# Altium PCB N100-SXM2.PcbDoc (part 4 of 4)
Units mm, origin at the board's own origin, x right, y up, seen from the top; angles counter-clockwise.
Board outline 120 x 145 mm, 4 copper layers (Top Layer, GND, PWR, Bottom Layer), stack 0.603 mm thick; 267 components, 207 nets, 1440 pads, 915 vias.
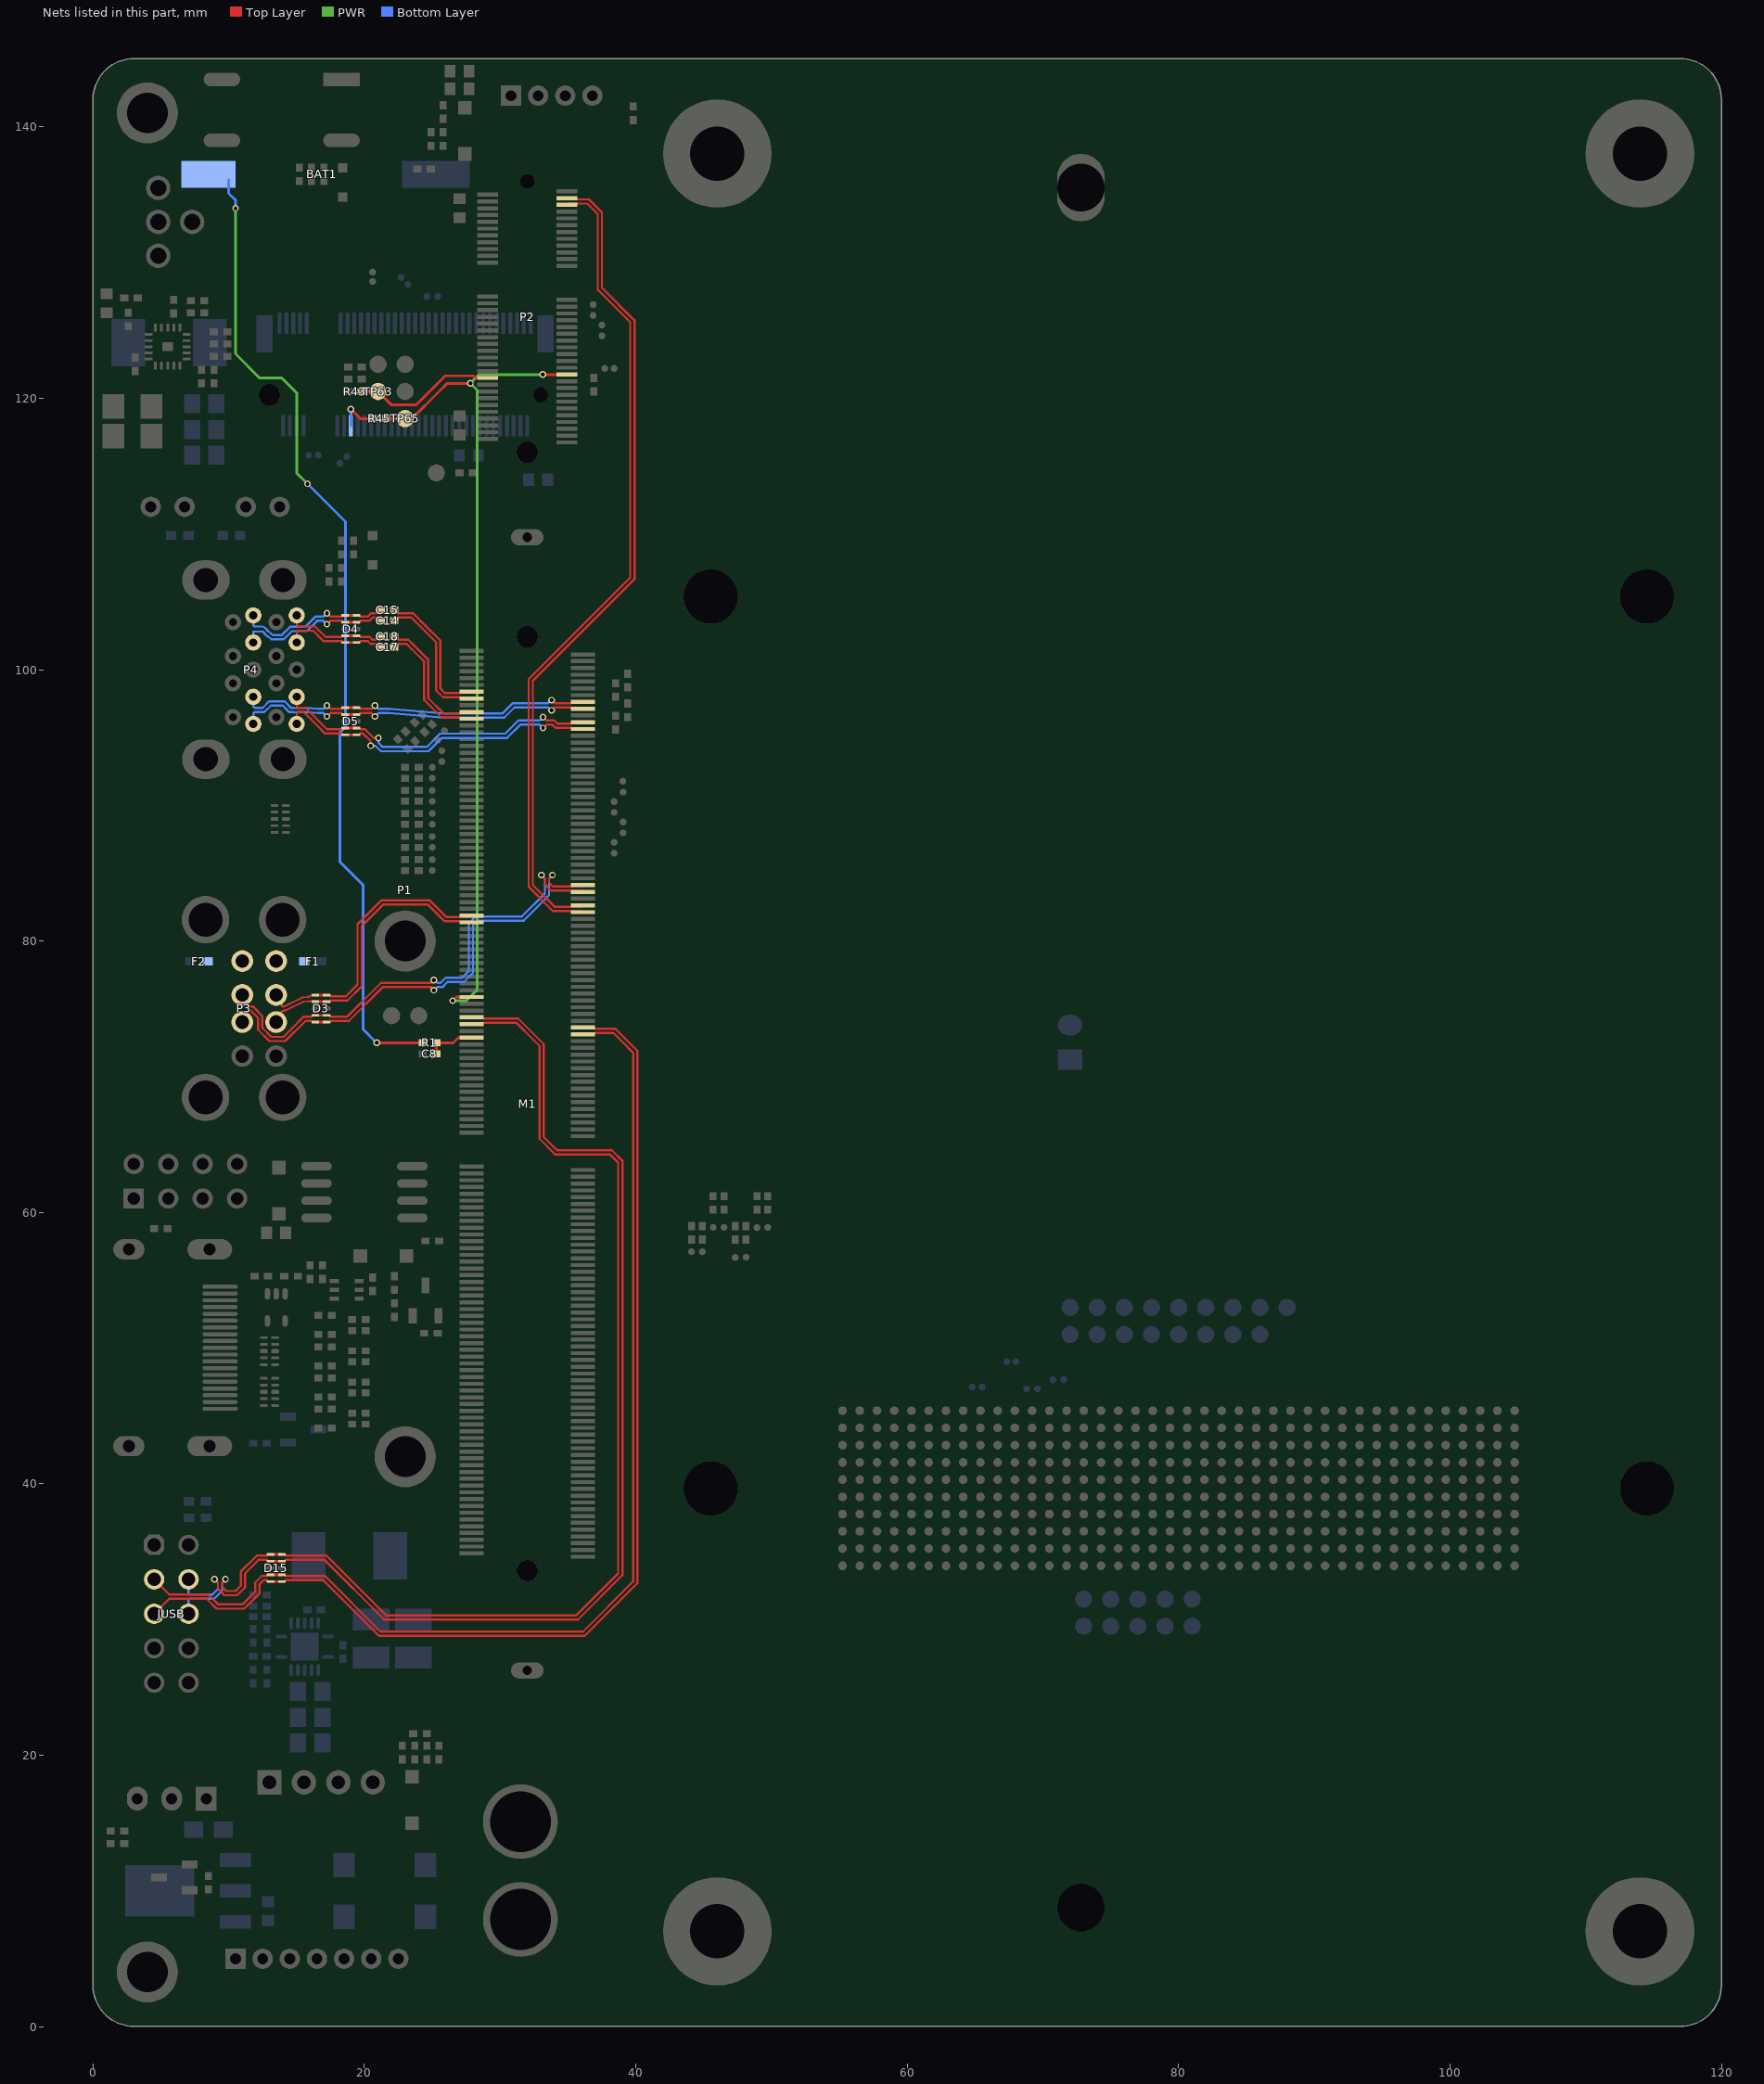
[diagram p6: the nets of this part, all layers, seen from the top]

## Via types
v1: diameter 0.5, hole 0.3, Top Layer to Bottom Layer, tented both sides, 908 vias
v2: diameter 0.6, hole 0.3, Top Layer to Bottom Layer, tented both sides, 6 vias
v3: diameter 1.5, hole 1.5, Top Layer to Bottom Layer, tented both sides, 1 vias

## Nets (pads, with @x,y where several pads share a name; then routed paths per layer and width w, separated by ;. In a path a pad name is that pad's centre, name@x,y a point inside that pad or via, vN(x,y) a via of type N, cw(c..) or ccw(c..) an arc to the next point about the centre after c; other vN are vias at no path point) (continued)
USB_3_n: D3.1 D3.10 M1.79 P3.2 | length 21.2
  Top Layer w0.161: P3.2@13.5,76.025 13.895,75.267 ccw(c14.037,75.342) 14.037,75.181 ; 14.038,75.181 ccw(c14.037,75.342) 14.1,75.193 15.353,75.806 cw(c15.491,75.528) 15.461,75.837 15.835,75.876 ; 15.836,75.876 ccw(c15.818,76.036) 15.877,75.886 16.18,76.006 D3.1@16.382,76.025 ; D3.10@17.218,76.025 17.401,76.025 17.495,75.931 18.631,75.931 19.489,76.789 19.489,81.229 21.271,83.011 24.789,83.011 25.092,82.708 25.2,82.6 26.02,81.78 27.011,81.78 27.036,81.805 27.831,81.805 M1.79@27.9,81.875
  Top Layer w0.2: D3.1@16.382,76.025 D3.10@17.218,76.025
USB_3_p: D3.2 D3.9 M1.81 P3.3 | length 21.2
  Top Layer w0.161: P3.3@13.5,74.025 13.895,74.783 ; 13.895,74.783 cw(c14.037,74.709) 14.037,74.87 ccw(c14.037,75.342) 14.221,74.907 ccw(c14.1,75.193) 14.237,74.914 15.491,75.528 15.867,75.566 cw(c15.883,75.406) 15.89,75.567 16.382,75.545 D3.2@16.382,75.525 ; D3.9@17.218,75.525 17.401,75.525 17.495,75.62 18.759,75.62 19.8,76.66 19.8,81.1 21.4,82.7 24.66,82.7 25.891,81.469 27.011,81.469 27.036,81.444 27.831,81.444 M1.81@27.9,81.375
  Top Layer w0.2: D3.2@16.382,75.525 D3.9@17.218,75.525
USB_4_n: D3.4 D3.7 M1.72 P3.6 | length 36.3
  Top Layer w0.161: P3.6@11,76.025 11,75.676 11.495,75.181 11.757,75.181 12.47,74.468 12.47,73.598 13.132,72.936 14.036,72.936 14.7,73.6 14.7,73.598 15.532,74.431 15.729,74.431 16.105,74.431 16.2,74.525 D3.4@16.382,74.525 ; D3.7@17.218,74.525 17.401,74.525 17.495,74.431 18.731,74.431 21.211,76.911 24.9,76.911 v1(25.12,77.131) ; v1(33.05,84.864) 33.05,84.844 33.295,84.6 33.295,84.171 33.746,83.719 35.211,83.719 35.236,83.694 36.03,83.694 M1.72@36.1,83.625
  Top Layer w0.2: D3.4@16.382,74.525 D3.7@17.218,74.525
  Bottom Layer w0.161: v1(25.12,77.131) 25.164,77.131 25.383,76.911 25.611,76.911 26,77.3 27.2,77.3 27.689,77.789 27.689,81.289 28.211,81.811 31.606,81.811 33.295,83.5 33.295,84.6 33.05,84.844 v1(33.05,84.864)
USB_4_p: D3.5 D3.6 M1.70 P3.7 | length 36.3
  Top Layer w0.161: P3.7@11,74.025 11,74.375 11.495,74.87 11.628,74.87 12.159,74.339 12.159,73.469 13.003,72.625 14.167,72.625 15.661,74.12 15.858,74.12 16.105,74.12 16.2,74.025 D3.5@16.382,74.025 ; D3.6@17.218,74.025 17.401,74.025 17.495,74.12 18.859,74.12 21.34,76.6 24.9,76.6 v1(25.12,76.381) ; v1(33.85,84.864) 33.85,84.844 33.606,84.6 33.606,84.3 33.875,84.03 35.211,84.03 35.236,84.055 36.03,84.055 M1.70@36.1,84.125
  Top Layer w0.2: D3.5@16.382,74.025 D3.6@17.218,74.025
  Bottom Layer w0.161: v1(25.12,76.381) 25.164,76.381 25.383,76.6 25.74,76.6 26.129,76.989 27.329,76.989 28,77.66 28,81.16 28.34,81.5 31.734,81.5 33.606,83.371 33.606,84.6 33.85,84.844 v1(33.85,84.864)
USB_B1_VBUS: F1.2 P3.1
USB_B2_VBUS: F2.2 P3.5
USB_F1_n: D15.2 D15.9 JUSB.4 M1.109 | length 90
  Top Layer w0.161: v1(8.955,32.964) 8.955,32.945 9.2,32.7 9.2,32.271 9.682,31.789 10.629,31.789 11.2,32.36 11.2,33.4 12.194,34.395 12.805,34.395 12.899,34.3 D15.2@13.082,34.3 ; D15.9@13.918,34.3 14.101,34.3 14.195,34.395 17.066,34.395 21.46,30 35.74,30 39.011,33.271 39.011,63.804 38.24,64.575 34.2,64.575 34.1,64.675 33.211,65.564 33.211,72.404 31.334,74.28 28.789,74.28 28.764,74.305 27.97,74.305 M1.109@27.9,74.375
  Top Layer w0.2: D15.2@13.082,34.3 D15.9@13.918,34.3
  Bottom Layer w0.161: JUSB.4@7.04,32.96 7.04,31.94 7.134,31.845 8.8,31.845 9.2,32.245 9.2,32.7 8.955,32.945 v1(8.955,32.964)
USB_F1_p: D15.1 D15.10 JUSB.6 M1.111 | length 88.9
  Top Layer w0.161: v1(9.755,32.964) 9.755,32.945 9.511,32.7 9.511,32.4 9.811,32.1 10.5,32.1 10.889,32.489 10.889,33.529 12.066,34.706 12.805,34.706 12.899,34.8 D15.1@13.082,34.8 ; D15.10@13.918,34.8 14.101,34.8 14.195,34.706 17.194,34.706 21.589,30.311 35.611,30.311 38.7,33.4 38.7,63.675 38.111,64.264 34.071,64.264 33.889,64.446 32.9,65.435 32.9,72.275 32.5,72.675 31.205,73.969 28.789,73.969 28.764,73.944 27.97,73.944 M1.111@27.9,73.875
  Top Layer w0.2: D15.1@13.082,34.8 D15.10@13.918,34.8
  Bottom Layer w0.161: JUSB.6@7.04,30.42 7.04,31.44 7.134,31.534 8.929,31.534 9.511,32.117 9.511,32.7 9.755,32.945 v1(9.755,32.964)
USB_F2_n: D15.4 D15.7 JUSB.3 M1.114 | length 83.9
  Top Layer w0.161: JUSB.3@4.5,32.96 5.615,31.845 8.494,31.845 9.229,31.111 11.011,31.111 11.959,32.059 11.959,32.735 12.429,33.206 12.805,33.206 12.899,33.3 D15.4@13.082,33.3 ; D15.7@13.918,33.3 14.101,33.3 14.195,33.206 17.094,33.206 21.189,29.111 36.111,29.111 39.8,32.8 39.8,71.775 39,72.575 38.355,73.219 37.216,73.219 36.989,73.219 36.964,73.194 36.169,73.194 M1.114@36.1,73.125
  Top Layer w0.2: D15.4@13.082,33.281 D15.7@13.918,33.281
USB_F2_p: D15.5 D15.6 JUSB.5 M1.112 | length 85
  Top Layer w0.161: JUSB.5@4.5,30.42 5.614,31.534 8.366,31.534 9.1,30.8 11.14,30.8 12.27,31.93 12.27,32.607 12.558,32.895 12.805,32.895 12.899,32.8 D15.5@13.082,32.8 ; D15.6@13.918,32.8 14.101,32.8 14.195,32.895 16.966,32.895 21.06,28.8 36.24,28.8 40.111,32.671 40.111,33.446 40.111,71.904 38.484,73.53 37.345,73.53 36.989,73.53 36.964,73.555 36.169,73.555 M1.112@36.1,73.625
  Top Layer w0.2: D15.5@13.082,32.8 D15.6@13.918,32.8
USB_M2_n: M1.78 P2.5 | length 61.1
  Top Layer w0.161: P2.5@34.93,134.25 34.999,134.319 35.694,134.319 35.719,134.344 36.423,134.344 37.189,133.578 37.189,128.011 39.589,125.611 39.589,106.789 32.1,99.3 32.1,84 33.881,82.219 35.211,82.219 35.236,82.194 36.03,82.194 M1.78@36.1,82.125
USB_M2_p: M1.76 P2.3 | length 61.1
  Top Layer w0.161: P2.3@34.93,134.75 34.999,134.681 35.694,134.681 35.719,134.655 36.552,134.655 37.5,133.707 37.5,128.14 39.9,125.74 39.9,106.66 32.411,99.171 32.411,84.129 34.009,82.53 35.211,82.53 35.236,82.555 36.03,82.555 M1.76@36.1,82.625
USBSS_1_RX_n: D5.4 D5.7 M1.18 P4.5 | length 26.5
  Top Layer w0.161: v1(17.236,96.55) 17.256,96.55 17.5,96.795 18.305,96.795 18.399,96.7 D5.7@18.582,96.7 ; D5.4@19.418,96.7 19.601,96.7 19.695,96.795 20.5,96.795 20.744,96.55 v1(20.764,96.55) ; v1(33.8,97) 34.019,97.219 35.193,97.219 cw(c35.193,97.177) 35.224,97.207 ccw(c35.254,97.237) 35.254,97.194 35.932,97.194 cw(c35.932,96.957) M1.18@36.1,97.125
  Top Layer w0.2: D5.7@18.582,96.7 D5.4@19.418,96.7
  Bottom Layer w0.161: P4.5@11.81,96.025 11.81,96.775 11.904,96.87 12.627,96.87 13.113,97.356 13.98,97.356 14.333,97.002 14.471,96.864 14.752,96.864 ccw(c14.91,97.994) 14.904,96.853 ccw(c14.91,98.411) 15.015,96.856 15.062,96.86 cw(c15.072,96.699) 15.066,96.86 15.07,96.86 ccw(c15.01,98) 15.168,96.87 15.641,96.87 16.574,96.796 ccw(c16.6,97.106) 16.599,96.795 ccw(c16.6,97.106) 16.6,96.794 16.972,96.795 17.217,96.55 v1(17.236,96.55) ; v1(20.764,96.55) 20.783,96.55 21.028,96.795 21.8,96.795 25.795,96.471 ccw(c25.821,96.78) 25.821,96.469 29.93,96.469 30.309,96.469 31.059,97.219 33.536,97.219 33.756,97 v1(33.8,97)
USBSS_1_RX_p: D5.5 D5.6 M1.16 P4.6 | length 26.5
  Top Layer w0.161: v1(17.236,97.35) 17.256,97.35 17.5,97.106 18.305,97.106 18.399,97.2 D5.6@18.582,97.2 ; D5.5@19.418,97.2 19.601,97.2 19.695,97.106 20.5,97.106 20.744,97.35 v1(20.764,97.35) ; v1(33.8,97.75) 34.02,97.53 35.194,97.53 ccw(c35.194,97.573) 35.224,97.543 cw(c35.254,97.513) 35.254,97.555 35.932,97.555 ccw(c35.932,97.793) M1.16@36.1,97.625
  Top Layer w0.2: D5.6@18.582,97.2 D5.5@19.418,97.2
  Bottom Layer w0.161: P4.6@11.81,98.025 11.81,97.275 11.904,97.181 12.498,97.181 12.984,97.667 14.108,97.667 14.6,97.175 14.775,97.175 ccw(c14.91,97.994) 14.909,97.164 ccw(c14.91,98.411) 15.03,97.17 ccw(c15.01,98) 15.145,97.181 15.641,97.181 cw(c15.641,97.025) 15.642,97.181 cw(c15.641,96.87) 15.667,97.179 16.6,97.106 16.972,97.106 17.217,97.35 v1(17.236,97.35) ; v1(20.764,97.35) 20.783,97.35 21.028,97.106 21.8,97.106 cw(c21.8,96.95) 21.802,97.105 cw(c21.8,96.794) 21.826,97.104 25.821,96.78 29.93,96.78 30.18,96.78 30.93,97.53 33.536,97.53 33.756,97.75 v1(33.8,97.75)
USBSS_1_TX_n: C14.2 M1.15 | length 10.3
  Top Layer w0.161: C14.2@22.2,103.6 22.246,103.6 22.49,103.845 23.455,103.845 24.517,102.783 25.289,102.011 25.289,98.471 25.791,97.969 26.994,97.969 cw(c26.994,97.927) 27.024,97.957 ccw(c27.054,97.987) 27.054,97.944 27.732,97.944 cw(c27.732,97.707) M1.15@27.9,97.875
USBSS_1_TX_p: C15.2 M1.13 | length 10.3
  Top Layer w0.161: C15.2@22.2,104.4 22.246,104.4 22.49,104.156 23.584,104.156 24.52,103.22 25.6,102.14 25.6,98.6 25.92,98.28 26.994,98.28 ccw(c26.994,98.323) 27.024,98.293 cw(c27.054,98.263) 27.054,98.305 27.732,98.305 ccw(c27.732,98.543) M1.13@27.9,98.375
USBSS_1a_TX_n: C14.1 D4.4 D4.7 P4.8 | length 11.4
  Top Layer w0.161: v1(17.236,103.35) 17.256,103.35 17.5,103.594 18.305,103.594 18.399,103.5 D4.7@18.582,103.5 ; D4.4@19.418,103.5 19.601,103.5 19.695,103.594 20.368,103.594 20.618,103.845 20.909,103.845 21.154,103.6 C14.1@21.2,103.6
  Top Layer w0.2: D4.7@18.582,103.5 D4.4@19.418,103.5
  Bottom Layer w0.161: P4.8@11.81,102.025 11.81,102.805 12.51,102.805 12.565,102.75 ccw(c13.478,103.435) 12.697,102.602 ccw(c15.466,105.563) 12.795,102.514 12.873,102.452 ccw(c14.727,104.805) 12.934,102.405 13.151,102.243 14.053,102.243 14.649,102.839 15.754,102.839 16.509,103.594 16.972,103.594 17.217,103.35 v1(17.236,103.35)
USBSS_1a_TX_p: C15.1 D4.5 D4.6 P4.9 | length 11.5
  Top Layer w0.161: v1(17.236,104.15) 17.256,104.15 17.5,103.905 18.305,103.905 18.399,104 D4.6@18.582,104 ; D4.5@19.418,104 19.601,104 19.695,103.905 20.239,103.905 20.489,104.156 20.909,104.156 21.154,104.4 C15.1@21.2,104.4
  Top Layer w0.2: D4.6@18.582,104 D4.5@19.418,104
  Bottom Layer w0.161: P4.9@11.81,104.025 11.81,103.275 11.904,103.181 12.476,103.181 12.639,103.116 12.801,102.953 ccw(c13.478,103.435) 12.914,102.825 ccw(c14.727,104.805) 13.264,102.554 13.924,102.554 14.521,103.15 15.625,103.15 16.38,103.905 16.972,103.905 17.217,104.15 v1(17.236,104.15)
USBSS_2_RX_n: D5.1 D5.10 M1.24 P4.14 | length 24.5
  Top Layer w0.161: P4.14@15.01,96.025 15.01,96.775 15.104,96.87 15.53,96.87 16.5,95.9 17.106,95.295 18.305,95.295 18.399,95.2 D5.10@18.582,95.2 ; D5.1@19.418,95.2 19.601,95.2 19.695,95.295 19.906,95.295 20.45,94.75 20.45,94.404 v1(20.464,94.391) ; v1(33.16,95.7) 33.179,95.7 33.424,95.944 33.854,95.944 34.079,95.719 35.211,95.719 35.236,95.694 36.03,95.694 M1.24@36.1,95.625
  Top Layer w0.2: D5.10@18.582,95.2 D5.1@19.418,95.2
  Bottom Layer w0.161: v1(20.464,94.391) 20.477,94.377 20.823,94.377 21.211,93.989 24.729,93.989 25.709,94.969 29.929,94.969 30.509,94.969 31.484,95.944 32.915,95.944 v1(33.16,95.7)
USBSS_2_RX_p: D5.2 D5.9 M1.22 P4.15 | length 24.5
  Top Layer w0.161: P4.15@15.01,98.025 15.01,97.275 15.104,97.181 15.659,97.181 17.234,95.606 18.305,95.606 18.399,95.7 D5.9@18.582,95.7 ; D5.2@19.418,95.7 19.601,95.7 19.695,95.606 20.034,95.606 20.67,94.97 21.016,94.97 v1(21.029,94.956) ; v1(33.16,96.5) 33.179,96.5 33.424,96.255 33.983,96.255 34.208,96.03 35.211,96.03 35.236,96.055 36.03,96.055 M1.22@36.1,96.125
  Top Layer w0.2: D5.9@18.582,95.7 D5.2@19.418,95.7
  Bottom Layer w0.161: v1(21.029,94.956) 21.043,94.943 21.043,94.597 21.34,94.3 24.6,94.3 25.58,95.28 29.93,95.28 30.38,95.28 31.355,96.255 32.915,96.255 v1(33.16,96.5)
USBSS_2_TX_n: C17.2 M1.21 | length 9.7
  Top Layer w0.161: C17.2@22.2,101.65 22.246,101.65 22.491,101.894 23.106,101.894 23.474,101.527 24.389,100.611 24.389,97.771 25.691,96.469 26.994,96.469 cw(c26.994,96.427) 27.024,96.457 ccw(c27.054,96.487) 27.054,96.444 27.732,96.444 cw(c27.732,96.207) M1.21@27.9,96.375
USBSS_2_TX_p: C18.2 M1.19 | length 9.7
  Top Layer w0.161: C18.2@22.2,102.45 22.246,102.45 22.491,102.205 23.234,102.205 23.62,101.82 23.795,101.645 24.609,100.831 24.7,100.74 24.7,97.9 25.82,96.78 26.994,96.78 ccw(c26.994,96.823) 27.024,96.793 cw(c27.054,96.763) 27.054,96.805 27.732,96.805 ccw(c27.732,97.043) M1.19@27.9,96.875
USBSS_2a_TX_n: C17.1 D4.1 D4.10 P4.17 | length 7.6
  Top Layer w0.161: P4.17@15.01,102.025 15.01,102.775 15.104,102.87 16.23,102.87 17.006,102.094 18.305,102.094 18.399,102 D4.10@18.582,102 ; D4.1@19.418,102 19.601,102 19.695,102.094 20.264,102.094 20.464,101.894 20.91,101.894 21.154,101.65 C17.1@21.2,101.65
  Top Layer w0.2: D4.10@18.582,102 D4.1@19.418,102
USBSS_2a_TX_p: C18.1 D4.2 D4.9 P4.18 | length 7.6
  Top Layer w0.161: P4.18@15.01,104.025 15.01,103.275 15.104,103.181 16.359,103.181 17.134,102.406 18.305,102.406 18.399,102.5 D4.9@18.582,102.5 ; D4.2@19.418,102.5 19.601,102.5 19.695,102.406 20.393,102.406 20.593,102.205 20.91,102.205 21.154,102.45 C18.1@21.2,102.45
  Top Layer w0.2: D4.9@18.582,102.5 D4.2@19.418,102.5
VBAT: BAT1.1 R1.1 | length 72.8
  Top Layer w0.2: v1(20.9,72.5) R1.1@24.3,72.5
  PWR w0.2: v1(10.5,134) 10.5,123.266 12.266,121.5 13.9,121.5 15,120.4 15,114.5 v1(15.8,113.7)
  Bottom Layer w0.2: BAT1.1@10,136.1 10,135.1 10.5,134.6 v1(10.5,134) ; v1(15.8,113.7) 18.6,110.9 18.6,95.766 18.2,95.366 18.2,85.834 19.9,84.134 19.9,73.5 v1(20.9,72.5)
VBAT_IN: C8.2 M1.115 R1.2 | length 3.6
  Top Layer w0.2: C8.2@25.3,71.7 R1.2@25.3,72.5 26.525,72.5 26.9,72.875 M1.115@27.9,72.875
WAKE#: M1.103 P2.55 R45.1 TP65.1 | length 63.2
  Top Layer w0.2: R45.1@21.6,118.5 TP65.1@23,118.5 23.5,118.5 25.5,120.5 26.1,121.1 v1(27.8,121.1) ; v1(26.5,75.6) 26.775,75.875 M1.103@27.9,75.875 ; v1(33.15,121.75) P2.55@34.93,121.75
  PWR w0.2: v1(26.5,75.6) 27.5,75.6 28.3,76.4 28.3,120.6 v1(27.8,121.1) 28.45,121.75 v1(33.15,121.75)
WAKE_M: P1.54 R45.2 | length 3.1
  Top Layer w0.2: v1(19,119.2) 19.7,118.5 R45.2@20.6,118.5
  Bottom Layer w0.2: P1.54@19,117.975 v1(19,119.2)
WLAN_OFF: P2.56 R43.2 TP63.1 | length 10.6
  Top Layer w0.2: R43.2@19.8,120.5 TP63.1@21,120.5 22,119.5 23.8,119.5 25.95,121.65 28.028,121.65 28.128,121.55 29.02,121.55 P2.56@29.07,121.5
pads on no net: D11.1 J2.1 J2.2 J2.3 J2.6 JUSB.9 JUSB.10 K1.2 K1.3 M1.7 M1.10 M1.12 M1.82 M1.84 M1.88 M1.90 M1.94 M1.96 M1.104 M1.117 M1.118 M1.119 M1.120 M1.121 M1.122 M1.123 M1.124 M1.125 M1.126 M1.127 M1.128 M1.129 M1.130 M1.132 M1.134 M1.137 M1.138 M1.139 M1.140 M1.141 M1.142 M1.143 M1.144 M1.145 M1.146 M1.147 M1.148 M1.149 M1.150 M1.152 M1.154 M1.156 M1.157 M1.160 M1.162 M1.164 M1.166 M1.168 M1.172 M1.173 M1.174 M1.175 M1.176 M1.177 M1.178 M1.179 M1.180 M1.184 M1.185 M1.186 M1.187 M1.190 M1.191 M1.192 M1.193 M1.196 M1.198 M1.202 M1.204 M1.208 M1.210 M1.214 M1.216 M1.220 M1.221 M1.222 M1.223 M1.226 M1.227 M1.228 M1.229 M1.232 M1.233 M1.234 M1.235 M1.238 M1.239 M1.240 M1.241 M1.244 M1.245 M1.246 M1.247 M1.261 P1.0 P1.5 P1.6 P1.7 P1.8 P1.11 P1.13 P1.17 P1.19 P1.20 P1.22 P1.23 P1.24 P1.25 P1.26 P1.28 P1.30 P1.32 P1.34 P1.36 P1.38 P1.40 P1.42 P1.44 P1.46 P1.48 P1.56 P1.58 P1.67 P1.68 P1.69 P2.0 P2.6 P2.8 P2.9 P2.10 P2.11 P2.12 P2.14 P2.15 P2.16 P2.17 P2.20 P2.21 P2.22 P2.23 P2.32 P2.34 P2.36 P2.38 P2.40 P2.42 P2.44 P2.46 P2.48 P2.58 P2.59 P2.60 P2.61 P2.62 P2.64 P2.65 P2.66 P2.67 P2.68 P2.70 P2.71 P2.73 P5.13 P5.14 P6.@45.5,39.675 P6.@45.5,105.375 P6.@46,7.025 P6.@46,138.025 P6.@72.8,8.775 P6.@72.8,135.525 P6.@114,138.025 P6.@114.5,39.675 P6.@114.5,105.375 P6.A2 P6.A3 P6.A5 P6.A6 P6.A8 P6.A9 P6.B1 P6.B2 P6.B4 P6.B5 P6.B9 P6.B10 P6.C2 P6.C3 P6.C5 P6.C6 P6.C8 P6.C9 P6.C15 P6.D1 P6.D2 P6.D4 P6.D5 P6.D9 P6.D10 P6.G1 P6.G2 P6.G4 P6.G5 P6.G9 P6.G10 P6.H2 P6.H3 P6.H5 P6.H6 P6.H8 P6.H9 P6.J1 P6.J2 P6.J4 P6.J5 P6.J7 P6.J9 P6.J10 P6.K2 P6.K3 P6.K5 P6.K6 P6.K8 P6.K9 P6.K39 U2.9 U2.11 U4.14
copper on no net:
  other v3: 1.7,133

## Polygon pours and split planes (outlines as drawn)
+3V3 on Top Layer "+3V3_L01_P159" (solid, pour order 159): 28.1,136.3 22,136.3 15.3,129.6 15.3,120 14.3,119 10.5,119 10.5,114.7 11.2,114 14.9,114 17.9,111 19.5,111 19.9,110.6 33.3,110.6 33.5,110.8 33.5,113.1 33.1,113.5 30.6,113.5 30,114.1 24.8,114.1 24.5,114.4 24.5,114.7 25.2,115.4 27.1,115.4 28.1,116.4 28.1,118 19.4,118 18.2,119.2 18.2,123.096 18.196,123.1 17.5,123.1 17.5,127.6 24,134.1 28.1,134.1
5V_HDMI on Top Layer "5V_HDMI_L01_P067" (solid, remove dead copper, pour order 67): 20.3,57.4 18.9,57.4 18,56.5 10.9,56.5 10.6,56.2 7,56.2 6.3,56.9 6.3,59 6.1,59.2 5.1,59.2 5.1,54.9 6.2,53.8 7.8,53.8 7.8,54.7 8,54.9 10.5,54.9 11.4,55.8 20.3,55.8
USB_1_VBUS on Top Layer "USB_1_VBUS_L01_P154" (solid, pour order 154): 7.7,113 5.2,113 5.2,111.6 4.7,111.1 4.7,103.5 5.7,102.5 10.7,102.5 11.1,102.9 11.1,103.8 10.2,104.7 7.3,104.7 6.3,105.7 6.3,111.1 6.4,111.2 7.7,111.2
USB_2_VBUS on Top Layer "USB_2_VBUS_L01_P153" (solid, pour order 153): 10.5,113 12.4,113 12.4,105.9 13.4,104.9 14.2,104.9 14.2,102.829 14.065,102.695 13.166,102.695 11.8,104.061 11.8,104.8 10.9,104.8 10.3,105.4 10.3,112.8
GND on Top Layer "GND_L01_P151" (solid, pour order 151): 0,129.1 9.5,129.1 10.3,128.3 15.1,128.3 15.1,129.7 21.9,136.5 24.3,136.5 24.3,145 0,145
GND on Top Layer "GND_L01_P145" (solid, pour order 145): 28.1,118.2 28.1,120.3 25.8,120.3 24.2,118.7 24.2,118.2 27.6,118.2
GND on Top Layer "GND_L01_P143" (solid, pour order 143): 19.7,123.3 20.3,123.9 28,123.9 28,128.2 21.2,128.2 20.1,127.1 17.6,127.1 17.7,127 17.7,123.3
GND on Top Layer "GND_L01_P142" (solid, pour order 142): 28,133.9 24.1,133.9 20.5,130.3 20.5,130 28,130
GND on Top Layer "GND_L01_P135" (solid, pour order 135): 0,0 0,29 10.7,29 13.2,31.5 17.3,31.5 20.7,28.1 39.9,28.1 42,30.2 42,44.2 42.6,44.8 45.3,44.8 48.5,41.6 48.5,31.7 51.7,28.5 67,28.5 69.8,31.3 69.8,35.1 81.2,35.1 81.2,31.6 69.3,19.7 41.2,19.7 33,11.5 26.4,11.5 25.3,10.4 25.3,0
GND on Top Layer "GND_L01_P127" (solid, remove dead copper, pour order 127): 3.2,125.7 7.5,125.7 7.5,115.2 3,115.2 3,121.4 2.8,121.6 2.8,123.7 3.2,124.1
3V3_SW on Top Layer "3V3_SW_L01_P126" (solid, remove dead copper, pour order 126): 3.7,126.3 5.2,126.3 5.2,123 4.9,122.7 4.9,121.3 4.4,121.3 3.7,122
+12V_IN on Top Layer "+12V_IN_L01_P125" (solid, remove dead copper, pour order 125): 4.4,124.4 3.1,124.4 2.7,124.8 0.5,124.8 0.5,108.6 2.8,108.6 2.8,121.3 2.6,121.5 2.6,122.4 2.8,122.6 3.6,122.6 3.8,122.8 4.4,122.8
+12V_IN on Top Layer "+12V_IN_L01_P117" (solid, remove dead copper, pour order 117): 5.5,65.5 5.5,85.9 4.5,86.9 4.5,108.2 1.7,111 0.5,111 0.5,65.5
GND on Top Layer "GND_L01_P115" (solid, remove dead copper, pour order 115): 1.2,59.2 11.5,59.2 11.5,41.5 1.2,41.5
GND on Top Layer "GND_L01_P095" (solid, remove dead copper, pour order 95): 54,51.5 81.2,51.5 81.2,32.8 54,32.8
+12V_IN on Top Layer "+12V_IN_L01_P059" (solid, remove dead copper, pour order 59): 25.5,0 25.5,10.3 26.5,11.3 33.1,11.3 41.3,19.5 69.375,19.5 81.4,31.525 81.4,51 119.5,51 119.5,12 111.9,12 109,9.1 109,0
+12V_CPU on Top Layer "NONET_L-01_P-001" (solid, remove dead copper, pour order 58): 36.975,34.475 27.025,34.475 27.025,37.025 32.025,37.025 32.275,37.275 36.975,37.275
GND on Bottom Layer "GND_L04_P158" (solid, pour order 158): 0,114.8 15.3,114.8 15.3,113.8 18.3,110.8 18.3,105.2 11,105.2 11,95 17.9,95 17.9,83 0,83
GND on Bottom Layer "GND_L04_P156" (solid, pour order 156): 0,125.8 17.8,125.8 17.8,127.5 18.3,128 20.8,128 23.5,130.7 38,130.7 38,145 0,145
USB_1_VBUS on Bottom Layer "USB_1_VBUS_L04_P155" (solid, pour order 155): 7.7,113 5.2,113 5.2,111.6 4.7,111.1 4.7,103.5 5.7,102.5 10.7,102.5 11.1,102.9 11.1,103.8 10.2,104.7 7.3,104.7 6.3,105.7 6.3,111.1 6.4,111.2 7.7,111.2
+3V3 on Bottom Layer "+3V3_L04_P149" (solid, pour order 149): 7.3,126 10.8,126 10.8,123 11,122.8 13.1,122.8 15.2,120.7 15.2,117.1 15.2,114.4 14.8,114 8.9,114 8.3,114.6 8.3,121 7.3,122 7.3,122.7
USB_2_VBUS on Bottom Layer "USB_2_VBUS_L04_P148" (solid, pour order 148): 10.5,113 12.4,113 12.4,105.9 13.4,104.9 14.2,104.9 14.2,102.829 14.065,102.695 13.166,102.695 11.8,104.061 11.8,104.8 10.9,104.8 10.3,105.4 10.3,112.8
GND on Bottom Layer "GND_L04_P147" (solid, pour order 147): 72.6,48.6 72.6,49.4 71,51 71,62 106.3,62 106.3,48.6
GND on Bottom Layer "GND_L04_P139" (solid, pour order 139): 27.6,116.9 19.3,116.9 19.3,115.9 23.9,111.3 23.9,102.2 27.2,102.2 30,105 30,110 27.6,112.4 27.6,114.6
+3V3 on Bottom Layer "+3V3_L04_P138" (solid, pour order 138): 27.8,118.9 34,118.9 34.3,118.6 34.3,111.5 33.5,110.7 29.6,110.7 27.8,112.5
GND on Bottom Layer "GND_L04_P137" (solid, pour order 137): 29.5,116 31.4,116 32.7,114.7 32.7,113.5 32.6,113.4 30.9,113.4 29.3,115 29.3,115.8
GND on Bottom Layer "NONET_L-01_P-001" (solid, remove dead copper, pour order 121): 11,123 34.3,123 34.3,127 11,127
GND on Bottom Layer "GND_L04_P134" (solid, remove dead copper, pour order 134): 0,0 0,83.5 29.9,83.5 29.9,78.5 30.7,77.7 45.6,77.7 62.7,60.6 62.7,49.2 64,47.9 64,46.7 64.2,46.5 72,46.5 72.6,47.1 72.6,49.2 120,49.2 120,0
+12V_IN on Bottom Layer "+12V_IN_L04_P132" (solid, remove dead copper, pour order 132): 27.2,10.7 17.7,10.7 17.4,11 17.4,16.9 16.9,17.4 16.9,19.2 16,20.1 16,25.6 15.8,25.8 15.8,26.7 14.4,26.7 14,26.3 14,24.9 13.1,24 13.1,19.4 13.3,19.2 14.1,19.2 14.2,19.1 14.2,10.4 15.4,9.2 19.4,9.2 19.6,9 19.6,6.3 27.2,6.3
+12V_CPU on Bottom Layer "+12V_CPU_L04_P131" (solid, remove dead copper, pour order 131): 26.8,10.9 26.8,21.3 30.5,25 30.5,27 30.9,27.4 30.9,34 31.9,35 31.9,36.8 31.6,37.1 28.1,37.1 26.9,35.9 26.9,29.5 25.8,28.4 25.8,25.9 22.3,22.4 22.3,16.3 20.5,14.5 17.6,14.5 17.6,10.9
+5V on Bottom Layer "+5V_L04_P130" (solid, remove dead copper, pour order 130): 7.8,39.3 9,40.5 20.1,40.5 23.8,36.8 25.1,36.8 26.7,35.2 26.7,29.6 25.8,28.7 18.6,28.7 18.6,36.7 18.1,37.2 12.7,37.2 12.2,36.7 8.1,36.7 7.8,37
GND on Bottom Layer "GND_L04_P128" (solid, remove dead copper, pour order 128): 8.1,114.8 8.1,120.9 7.1,121.9 7.1,127.6 0,127.6 0,114.8
3V3_SW on Bottom Layer "3V3_SW_L04_P124" (solid, remove dead copper, pour order 124): 5.1,126.3 5.3,126.1 5.3,125 5.1,124.8 5.1,122.1 4.9,121.9 4.9,121.5 4.7,121.3 2.2,121.3 1.2,122.3 1.2,126.1 1.4,126.3
5V_SW on Bottom Layer "5V_SW_L04_P122" (solid, remove dead copper, pour order 122): 16.3,29.3 16.3,31 16.5,31.2 17.7,31.2 17.7,36.8 13.9,36.8 13.9,31.5 14.5,30.9 14.9,30.9 15.4,30.4 15.4,29.3
FUSB_VBUS2 on Bottom Layer "FUSB_VBUS2_L04_P113" (solid, remove dead copper, pour order 113): 5.6,34.7 5.6,37.7 6.1,38.2 7.6,38.2 7.6,39.3 5.5,39.3 3.5,37.3 3.5,34.7 3.9,34.3 5.2,34.3
FUSB_VBUS1 on Bottom Layer "FUSB_VBUS1_L04_P112" (solid, remove dead copper, pour order 112): 7.7,34.3 8.2,34.8 8.2,36.1 7.6,36.7 7.6,38 6.3,38 6,37.7 6,34.7 6.4,34.3
USB_B1_VBUS on Bottom Layer "USB_B1_VBUS_L04_P107" (solid, remove dead copper, pour order 107): 12.5,79.5 12.5,77.5 16.1,77.5 16.1,79.5
USB_B2_VBUS on Bottom Layer "USB_B2_VBUS_L04_P106" (solid, remove dead copper, pour order 106): 12,77.5 12,79.5 8,79.5 8,77.5
+3V3_SB on Bottom Layer "+3V3_SB_L04_P104" (solid, remove dead copper, pour order 104): 9,7 9,8.4 9.3,8.7 12,8.7 12,11.3 9.2,11.3 8.4,12.1 8.4,15.3 1.5,15.3 1.5,7.4 1.9,7
+12V_IN on Bottom Layer "+12V_IN_L04_P061" (solid, remove dead copper, pour order 61): 27,11.3 36,11.3 37.1,12.4 44.2,19.5 74.4,19.5 81.4,26.5 81.4,42 119.5,42 119.5,12 111.9,12 109,9.1 109,0.3 27,0.3
no net on Bottom Layer "NONET_L-01_P-001" (solid, remove dead copper, pour order 16): 112.9,12.725 112.9,13.525 cw(c113.3,13.525) 113.3,13.925 114.1,13.925 cw(c114.1,13.525) 114.5,13.525 114.5,12.725 cw(c114.1,12.725) 114.1,12.325 113.3,12.325 cw(c113.3,12.725)
GND on PWR "NONET_L-01_P-001" (solid, remove dead copper, pour order 157): 0,0 120,0 120,145 0,145
+5V on PWR "+5V_L03_P152" (solid, pour order 152): 14.5,77 0,77 0,111 10.5,111 10.5,105.5 9.2,104.2 9.2,97.8 11.8,95.2 11.8,92.3 14.5,89.6 14.5,86.8
+5V on PWR "+5V_L03_P118" (solid, remove dead copper, pour order 118): 5.5,77 5.5,91.5 15.8,91.5 28,91.5 28,35.1 30.7,32.4 58.3,32.4 60.2,30.5 72.3,30.5 73.3,29.5 78.5,29.5 79,30 79,38.4 78.3,39.1 78.3,39.9 78.6,40.2 82.1,40.2 82.7,39.6 82.7,33.3 84.2,31.8 84.2,27.2 79.9,22.9 27.4,22.9 18.5,31.8 18.5,48.1 18.5,73 14.5,77
+12V_IN on PWR "+12V_IN_L03_P119" (solid, remove dead copper, pour order 119): 0,68.5 4.9,68.5 7,66.4 18.3,66.4 18.3,28.4 24,22.7 24,14.9 27.9,11 33.8,11 35,9.8 35,4.1 34.3,3.4 26.3,3.4 23.4,6.3 7.7,6.3 6.2,7.8 0,7.8
GND on GND "NONET_L-01_P-001" (solid, remove dead copper, pour order 60): 0,0 120,0 120,145 0,145

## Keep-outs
Keep-Out Layer:
  circle w0.1: c45.5,39.675 r2.5
  circle w0.1: c114.5,39.675 r2.5
  lines w0.1: 0,3.025 ccw(c3,3.025) 3,0.025 117,0.025 ccw(c117,3.025) 120,3.025 120,142.025 ccw(c117,142.025) 117,145.025 3,145.025 ccw(c3,142.025) 0,142.025 0,3.025

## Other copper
Top Layer:
  drawing of 2289 lines, arcs and shapes, not listed
GND:
  region net +5V: 10.1,111 6.5,111 6.5,108.8 10.1,108.8
  rectangle net +3V3: 30.2,111 33.2,113.2
  rectangle net +12V_IN: 0.7,65.7 3.4,67.7
  rectangle net +3V3: 11.3,115.4 13.3,118.1
  rectangle net +5V: 17,77.5 18.4,79.5
  rectangle net +5V: 6.1,77.5 7.5,79.5
  rectangle net +12V_IN: 21.2,7.3 23.4,10.3
  rectangle net +12V_CPU: 29.7,34.8 31.7,36.8
  rectangle net +5V: 23.4,31.2 26.4,34.2
  region net 3V3_SW: 4.4,126.3 5,126.3 cw(c5,126) 5.3,126 5.3,125.4 5.1,125.2 5.1,122.6 4.9,122.4 4.9,121.6 cw(c4.6,121.6) 4.6,121.3 cw(c4.6,121.541) 4.429,121.371 4.012,121.788 cw(c4.524,122.3) 3.8,122.3 3.8,125.517 cw(c4.483,125.517) 4,126 4.229,126.229 cw(c4.4,126.059)
  pour cut-out: 48.675,59.9 48.675,61.5 49.175,61.5 49.175,59.9
  pour cut-out: 49.475,59.9 49.475,61.5 49.975,61.5 49.975,59.9
  pour cut-out: 47.075,57.7 47.075,59.3 47.575,59.3 47.575,57.7
  pour cut-out: 47.875,57.7 47.875,59.3 48.375,59.3 48.375,57.7
  pour cut-out: 45.45,59.9 45.45,61.5 45.95,61.5 45.95,59.9
  pour cut-out: 46.25,59.9 46.25,61.5 46.75,61.5 46.75,59.9
  pour cut-out: 25.026,95.577 23.895,96.708 24.248,97.062 25.38,95.93
  pour cut-out: 24.46,95.011 23.329,96.142 23.683,96.496 24.814,95.365
  pour cut-out: 23.206,93.775 22.075,94.906 22.428,95.26 23.56,94.128
  pour cut-out: 23.772,94.34 22.64,95.472 22.994,95.825 24.125,94.694
  pour cut-out: 22.7,86.25 24.3,86.25 24.3,85.75 22.7,85.75
  pour cut-out: 22.7,85.45 24.3,85.45 24.3,84.95 22.7,84.95
  pour cut-out: 22.7,87.95 24.3,87.95 24.3,87.45 22.7,87.45
  pour cut-out: 22.7,87.15 24.3,87.15 24.3,86.65 22.7,86.65
  pour cut-out: 22.7,92.275 24.3,92.275 24.3,91.775 22.7,91.775
  pour cut-out: 22.7,93.075 24.3,93.075 24.3,92.575 22.7,92.575
  pour cut-out: 22.7,90.575 24.3,90.575 24.3,90.075 22.7,90.075
  pour cut-out: 22.7,91.375 24.3,91.375 24.3,90.875 22.7,90.875
  pour cut-out: 22.7,88.85 24.3,88.85 24.3,88.35 22.7,88.35
  pour cut-out: 22.7,89.65 24.3,89.65 24.3,89.15 22.7,89.15
  region net +12V_IN: 83.429,41.072 83.429,38.278 82.667,37.516 82.413,37.516 81.651,38.278 81.651,41.072 82.413,41.834 82.667,41.834
  region net +12V_IN: 87.239,41.072 87.239,38.278 86.477,37.516 86.223,37.516 85.461,38.278 85.461,41.072 86.223,41.834 86.477,41.834
  region net +12V_IN: 91.049,41.072 91.049,38.278 90.287,37.516 90.033,37.516 89.271,38.278 89.271,41.072 90.033,41.834 90.287,41.834
  region net +12V_IN: 94.859,41.072 94.859,38.278 94.097,37.516 93.843,37.516 93.081,38.278 93.081,41.072 93.843,41.834 94.097,41.834
  region net +12V_IN: 98.669,41.072 98.669,38.278 97.907,37.516 97.653,37.516 96.891,38.278 96.891,41.072 97.653,41.834 97.907,41.834
  region net +12V_IN: 102.479,41.072 102.479,38.278 101.717,37.516 101.463,37.516 100.701,38.278 100.701,41.072 101.463,41.834 101.717,41.834
  pour cut-out: 44.65,57.7 44.65,59.3 45.15,59.3 45.15,57.7
  pour cut-out: 43.85,57.7 43.85,59.3 44.35,59.3 44.35,57.7
PWR:
  rectangle net +3V3: 30.2,111 33.2,113.2
  rectangle net +3V3: 11.3,115.4 13.3,118.1
  rectangle net +12V_CPU: 29.7,34.8 31.7,36.8
  region net 3V3_SW: 4.4,126.3 5,126.3 cw(c5,126) 5.3,126 5.3,125.4 5.1,125.2 5.1,122.6 4.9,122.4 4.9,121.6 cw(c4.6,121.6) 4.6,121.3 cw(c4.6,121.541) 4.429,121.371 4.012,121.788 cw(c4.524,122.3) 3.8,122.3 3.8,125.517 cw(c4.483,125.517) 4,126 4.229,126.229 cw(c4.4,126.059)
  region net GND: 17.9,26.6 18.5,26 24,26 24.2,25.8 24.2,24.9 24,24.7 18.8,24.7 18.4,24.3 18.4,23.4 18.2,23.2 18,23.2 17.8,23.4 17.8,25.1 17.5,25.4 17,25.4 16.8,25.6 16.8,26.4 17,26.6
  region net GND: 15.7,29 16.6,28.1 16.6,27.9 15.7,27 15.5,27 14.6,27.9 14.6,28.1 15.5,29
  region net +12V_IN: 102.479,41.072 102.479,38.278 101.717,37.516 101.463,37.516 100.701,38.278 100.701,41.072 101.463,41.834 101.717,41.834
  region net +12V_IN: 98.669,41.072 98.669,38.278 97.907,37.516 97.653,37.516 96.891,38.278 96.891,41.072 97.653,41.834 97.907,41.834
  region net +12V_IN: 94.859,41.072 94.859,38.278 94.097,37.516 93.843,37.516 93.081,38.278 93.081,41.072 93.843,41.834 94.097,41.834
  region net +12V_IN: 91.049,41.072 91.049,38.278 90.287,37.516 90.033,37.516 89.271,38.278 89.271,41.072 90.033,41.834 90.287,41.834
  region net +12V_IN: 87.239,41.072 87.239,38.278 86.477,37.516 86.223,37.516 85.461,38.278 85.461,41.072 86.223,41.834 86.477,41.834
  region net +12V_IN: 83.429,41.072 83.429,38.278 82.667,37.516 82.413,37.516 81.651,38.278 81.651,41.072 82.413,41.834 82.667,41.834
Bottom Layer:
  drawing of 1590 lines, arcs and shapes, not listed
  text "20250211-REV.A2" at 118.525,70.748 h5 r90

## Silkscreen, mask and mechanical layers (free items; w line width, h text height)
Top Overlay:
  drawing of 81 lines, arcs and shapes, not listed
  text "RESET" at 20.127,144.513 h2.5 r270
  text "PWR SW" at 10.027,137.416 h2.5 r270
  text "CPU_FAN" at 28.634,137.244 h2.5
  text "M.2 E-KEY" at 25.2,131.432 h2.5 r270
  text "M.2_SSD ACT" at 3.9,126.9 h1.52
  text "PERST#" at 15.5,124.5 h1.5
  text "CLKREQ" at 22.6,112.5 h1.52
  text "DATA" at 19.1,75.5 h1.52
  text "CLK" at 23,75.5 h1.52
  text "SMBus" at 18.7,72.7 h1.52
  text "JBIOS" at 11.795,29.127 h2.5
  text "1-2 INT ROM" at 11.8,26.827 h2.5
  text "2-3 EXT ROM" at 11.798,24.629 h2.5
  text "SYS_FAN" at 11.906,21.408 h2.5
  text "GND" at 36.2,17.363 h2.5 r270
  text "12V-MAIN" at 25.197,16.438 h2.5 r270
  text "12VSB" at 17.7,14.096 h2.5 r270
  text "3" at 2.9,13.523 h2
  text "2" at 5.398,13.5 h2
  text "1" at 8,13.5 h2
  text "PSON" at 15.7,13.487 h2.5 r270
  text "GND" at 9.7,12.227 h2.5 r270
  text "GND" at 11.7,12.227 h2.5 r270
  text "GND" at 13.7,12.227 h2.5 r270
  text "GND" at 19.7,12.227 h2.5 r270
  text "GND" at 21.7,12.227 h2.5 r270
  text "+12V" at 36.197,10.569 h2.5 r270
Bottom Overlay:
  drawing of 481 lines, arcs and shapes, not listed
  text "CR1220" at 28.34,131 h3 r270
  text "M.2 NVME SSD" at 23.76,108 h3 r90
  text "TP_B16" at 71.652,54 h1.5 r270
  text "TP_A16" at 73.652,54 h1.5 r270
  text "TP_B17" at 75.652,54 h1.5 r270
  text "JSEL" at 77.52,53.997 h1.5 r270
  text "JTDO" at 79.52,53.997 h1.5 r270
  text "JTCK" at 81.52,53.997 h1.5 r270
  text "JTMS" at 83.52,53.997 h1.5 r270
  text "JRST" at 85.52,53.997 h1.5 r270
  text "ADDR1" at 87.518,53.999 h1.5 r270
  text "JTDI" at 79.528,47.327 h1.5 r270
  text "OVERT" at 83.52,45.474 h1.5 r270
  text "TP_A15" at 72.152,45.242 h1.5 r270
  text "TP_D16" at 73.652,45.175 h1.5 r270
  text "TP_C16" at 75.645,45.175 h1.5 r270
  text "TP_D17" at 77.652,45.175 h1.5 r270
  text "PWR_EN" at 81.653,44.48 h1.5 r270
  text "PWR_BREAK" at 85.653,41.69 h1.5 r270
  text "TP_H15" at 72.652,32.5 h1.5 r270
  text "TP_K16" at 74.652,32.5 h1.5 r270
  text "TP_G17" at 76.645,32.5 h1.5 r270
  text "TP_H16" at 78.652,32.5 h1.5 r270
  text "ADDR0" at 80.526,32.499 h1.5 r270
  text "TP_k15" at 72.652,23.965 h1.5 r270
  text "TP_J16" at 74.652,23.973 h1.5 r270
  text "TP_J17" at 78.652,23.973 h1.5 r270
  text "TP_G16" at 76.645,23.6 h1.5 r270
  text "PWRGD" at 80.52,23.537 h1.5 r270
Mechanical 1:
  lines w0.1: 0,3.025 ccw(c3,3.025) 3,0.025 117,0.025 ccw(c117,3.025) 120,3.025 120,142.025 ccw(c117,142.025) 117,145.025 3,145.025 ccw(c3,142.025) 0,142.025 0,3.025
  lines w0.2: 76,70 ccw(c77,70) 77,69 83,69 ccw(c83,70) 84,70 84,75 ccw(c83,75) 83,76 77,76 ccw(c77,75) 76,75 76,70
Mechanical 15:
  lines w0.1: 78.15,39.675 81.85,39.675 ; 80,37.825 80,41.525 ; 80,39.675 82.5,42 102.5,42
  lines w0.2: 34,115 5,115 5,137 34,137
  text "SXM2 PLUG REF" at 82.954,42.754 h1.52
